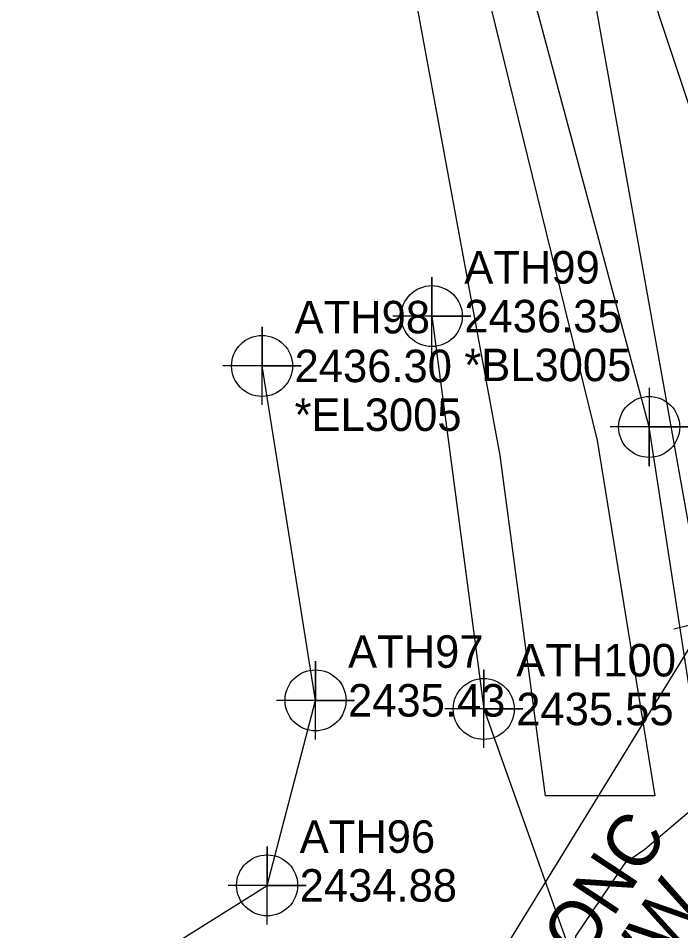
# Model space of a CAD drawing. Extents: x 983976 to 986421, y 758828 to 761458.
# Drawn here: x 984771.6 to 984822.5, y 760119.1 to 760189.2 of the extents above; entities that cross this region are included whole.
import ezdxf

# ---------------------------------------------------------------- set-up
doc = ezdxf.new("R2010")
doc.units = 0
for name, color, linetype in [('Exist Hydro Jurisdictional Stream or Body of Water', 7, 'Continuous'), ('Exist Property Corner CELL', 7, 'Continuous'), ('Exist Property Line', 7, 'Continuous'), ('Exist Right of Way Line', 7, 'Continuous'), ('Exist Roads Soil', 7, 'Continuous'), ('Exist Roads Soil Cogo Comment', 7, 'Continuous'), ('Exist Roads Soil Cogo Elevation', 7, 'Continuous'), ('Exist Roads Soil Cogo Number', 7, 'Continuous'), ('Exist Roads Soil Cogo Point CELL', 7, 'Continuous'), ('Exist Structure Major Bridge WW Text', 7, 'Continuous'), ('Exist Utilities Power Transformer CELL', 7, 'Continuous'), ('Exist Utilities Telephone UG Cable SUE LOS C', 7, 'Continuous'), ('Exist Vegetation Hedge Row', 7, 'Continuous')]:
    doc.layers.add(name, color=color, linetype=linetype)

msp = doc.modelspace()

# ---------------------------------------------------------------- linework, layer by layer
at = {"layer": 'Exist Hydro Jurisdictional Stream or Body of Water'}
for points in [[(984827.066, 760112.31), (984826.358, 760116.652), (984820.043, 760157.784), (984809.834, 760195.884), (984798.987, 760237.514), (984800.737, 760260.977), (984804.203, 760288.203), (984847.36, 760365.08), (984869.621, 760385.916), (984871.863, 760387.268)], [(984833.783, 760122.599), (984833.36, 760124.895), (984829.257, 760164.033), (984817.971, 760197.997), (984808.33, 760238.739), (984808.895, 760259.215), (984814.879, 760280.8), (984849.913, 760355.964), (984876.591, 760379.37), (984877.556, 760380.016)]]:
    msp.add_lwpolyline(points, dxfattribs=at)
at = {"layer": 'Exist Property Corner CELL'}
msp.add_lwpolyline([(984823.793, 760145.258), (984824.956, 760140.395), (984824.374, 760142.826), (984826.806, 760143.408), (984821.943, 760142.245)], dxfattribs=at)
at = {"layer": 'Exist Property Line'}
msp.add_line((984800.106, 760279.119), (984824.374, 760142.826), dxfattribs=at)
at = {"layer": 'Exist Right of Way Line'}
msp.add_line((984764.902, 760045.927), (984824.404, 760142.874), dxfattribs=at)
at = {"layer": 'Exist Roads Soil'}
for points in [[(984803.344, 760166.306), (984807.335, 760136.106), (984821.037, 760097.548)], [(984793.775, 760052.751), (984788.471, 760073.954), (984778.391, 760065.613), (984773.513, 760069.958), (984778.161, 760075.844), (984778.778, 760078.208), (984778.292, 760079.381), (984782.099, 760083.373), (984774.015, 760112.062), (984790.697, 760122.544), (984794.413, 760136.769), (984790.306, 760162.479)]]:
    msp.add_lwpolyline(points, dxfattribs=at)
at = {"layer": 'Exist Roads Soil Cogo Point CELL'}
for points in [[(984803.344, 760163.306), (984803.344, 760169.306), (984803.344, 760166.306), (984806.344, 760166.306), (984800.344, 760166.306)], [(984790.306, 760159.479), (984790.306, 760165.479), (984790.306, 760162.479), (984793.306, 760162.479), (984787.306, 760162.479)], [(984794.413, 760133.769), (984794.413, 760139.769), (984794.413, 760136.769), (984797.413, 760136.769), (984791.413, 760136.769)], [(984807.335, 760133.106), (984807.335, 760139.106), (984807.335, 760136.106), (984810.335, 760136.106), (984804.335, 760136.106)], [(984790.697, 760119.544), (984790.697, 760125.544), (984790.697, 760122.544), (984793.697, 760122.544), (984787.697, 760122.544)]]:
    msp.add_lwpolyline(points, dxfattribs=at)
for centre in [(984803.344, 760166.306), (984790.306, 760162.479), (984794.413, 760136.769), (984807.335, 760136.106), (984790.697, 760122.544)]:
    msp.add_circle(centre, 2.344, dxfattribs=at)
at = {"layer": 'Exist Utilities Power Transformer CELL'}
msp.add_lwpolyline([(984820.043, 760160.784), (984820.043, 760154.784), (984820.043, 760157.784), (984823.043, 760157.784), (984817.043, 760157.784)], dxfattribs=at)
msp.add_circle((984820.043, 760157.784), 2.344, dxfattribs=at)
at = {"layer": 'Exist Utilities Telephone UG Cable SUE LOS C'}
msp.add_lwpolyline([(984735.48, 759996.35), (984742.018, 759994.164), (984745.761, 759995.104), (984748.488, 759998.937), (984763.623, 760023.792), (984778.86, 760050.581), (984792.164, 760067.072), (984808.722, 760086.443), (984818.045, 760100.742), (984814.058, 760115.562), (984814.401, 760118.642), (984818.244, 760124.329), (984819.704, 760125.325), (984838.189, 760141.042), (984839.77, 760142.811), (984839.369, 760146.124)], dxfattribs=at)
at = {"layer": 'Exist Vegetation Hedge Row'}
msp.add_lwpolyline([(984803.223, 760209.047), (984816.057, 760156.751), (984820.49, 760129.436), (984812.09, 760129.436), (984808.59, 760155.584), (984801.59, 760193.638), (984792.475, 760228.001), (984788.013, 760269.966), (984797.846, 760304.143), (984830.104, 760351.536), (984840.313, 760358.89), (984809.687, 760308.229), (984798.254, 760285.349), (984794.17, 760235.505), (984803.223, 760209.047)], dxfattribs=at)

# ---------------------------------------------------------------- texts
at = {"layer": 'Exist Roads Soil Cogo Comment'}
for s, p in [('*BL3005', (984805.844, 760161.306)), ('*EL3005', (984792.806, 760157.479))]:
    msp.add_text(s, height=2.5, dxfattribs=at).set_placement(p)
at = {"layer": 'Exist Roads Soil Cogo Elevation'}
for s, p in [('2436.35', (984805.844, 760165.056)), ('2436.30', (984792.806, 760161.229)), ('2435.43', (984796.913, 760135.519)), ('2435.55', (984809.835, 760134.856)), ('2434.88', (984793.197, 760121.294))]:
    msp.add_text(s, height=2.5, dxfattribs=at).set_placement(p)
at = {"layer": 'Exist Roads Soil Cogo Number'}
for s, p in [('ATH99', (984805.844, 760168.806)), ('ATH98', (984792.806, 760164.979)), ('ATH97', (984796.913, 760139.269)), ('ATH100', (984809.835, 760138.606)), ('ATH96', (984793.197, 760125.044))]:
    msp.add_text(s, height=2.5, dxfattribs=at).set_placement(p)
at = {"layer": 'Exist Structure Major Bridge WW Text'}
for s, p in [('CONC', (984812.793, 760113.32)), (' WW', (984817.905, 760111.525))]:
    msp.add_text(s, height=4, rotation=56.34707, dxfattribs=at).set_placement(p)

doc.saveas('drawing.dxf')
